(* Logix 5000 project; controller EFlo_iQ_Controller vendor 1 type 14 code 74 rev 20.12; software revision 20.01 *)

TASK MainTask (continuous, watchdog 500 ms) : MainProgram

MODULES
   Local : vendor 1 type 14 code 74 (1768Ctrl5Slot 0, Compact 0, rev 20.12)
      ENET : 1768-ENBT (1768 1, Ethernet 10.10.20.11, rev 3.1)
         EFlo_iQ : ETHERNET-MODULE (Ethernet 10.10.20.16, rev 1.1, Output RPI 10 ms)   // Graco E-Flo iQ Pico Map
END_MODULES

TYPE EFlo_iQ_Control_Bits :
STRUCT
   SystemEnableRequest : BOOL;
   SystemDisableRequest : BOOL;
   PLCLockoutRequest : BOOL;
   StyleEnableSignal : BOOL;
   StyleGoSignal : BOOL;
   StyleDispenseCompleted : BOOL;
   TandemCrossoverRequest : BOOL;
END_STRUCT
END_TYPE

TYPE EFlo_iQ_HeartbeatLogic :
STRUCT
   HeartbeatFailure : BOOL;
   EFlo_iQ_Disconnected : BOOL;
   Heartbeat_HighMonitor : COUNTER;
   Heartbeat_LowMonitor : COUNTER;
   Heartbeat_MonitorTimer : TIMER;
   Heartbeat_StopMonitorTimer : BOOL;
END_STRUCT
END_TYPE

TYPE EFlo_iQ_Status_Bits :
STRUCT
   Heartbeat : BOOL;
   AutomationReady : BOOL;
   PLCControlActive : BOOL;
   SystemActive : BOOL;
   NoAlarmsPresent : BOOL;
   NoDeviationsPresent : BOOL;
   NoAdvisoriesPresent : BOOL;
   SystemReady : BOOL;
   PrechargeDechargeActive : BOOL;
   DispenseInProcess : BOOL;
   DrumIsLow : BOOL;
   DrumIsEmpty : BOOL;
   PumpNotPrimed : BOOL;
END_STRUCT
END_TYPE

TYPE EFlo_iQ_StyleRequest :
STRUCT
   DesiredStyleNumber : DINT;
   DesiredStylePrecharge : DINT;   // XXXX.X bars
   DesiredStyleFlowrate : DINT;   // XXXX cc/min
   DesiredStyleShot : DINT;   // XXXX.XX cc
END_STRUCT
END_TYPE

VAR_GLOBAL   (* controller tags *)
   EFlo_iQ_Control_Bits : EFlo_iQ_Control_Bits; {access Read Only}
   EFlo_iQ_HeartbeatLogic : EFlo_iQ_HeartbeatLogic := (Heartbeat_HighMonitor.PRE := 2, Heartbeat_LowMonitor.PRE := 2, Heartbeat_MonitorTimer.PRE := 20000); {access Read Only}
   EFlo_iQ_Status_Bits : EFlo_iQ_Status_Bits; {access Read Only}
   EFlo_iQ_StyleRequest : EFlo_iQ_StyleRequest; {access Read Only}
END_VAR

PROGRAM MainProgram   (* main routine MainRoutine *)

ROUTINE MainRoutine   (* ladder *)
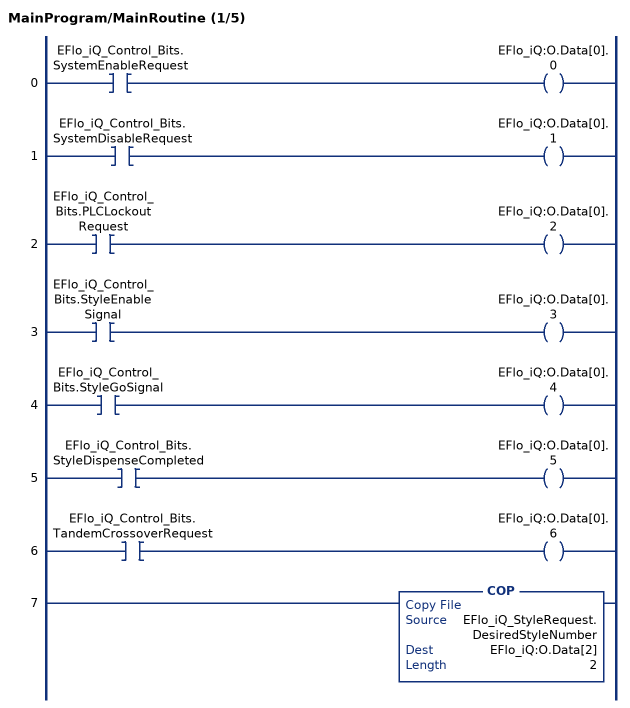
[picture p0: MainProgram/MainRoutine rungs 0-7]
   0: XIC(EFlo_iQ_Control_Bits.SystemEnableRequest)OTE(EFlo_iQ:O.Data[0].0);
   1: XIC(EFlo_iQ_Control_Bits.SystemDisableRequest)OTE(EFlo_iQ:O.Data[0].1);
   2: XIC(EFlo_iQ_Control_Bits.PLCLockoutRequest)OTE(EFlo_iQ:O.Data[0].2);
   3: XIC(EFlo_iQ_Control_Bits.StyleEnableSignal)OTE(EFlo_iQ:O.Data[0].3);
   4: XIC(EFlo_iQ_Control_Bits.StyleGoSignal)OTE(EFlo_iQ:O.Data[0].4);
   5: XIC(EFlo_iQ_Control_Bits.StyleDispenseCompleted)OTE(EFlo_iQ:O.Data[0].5);
   6: XIC(EFlo_iQ_Control_Bits.TandemCrossoverRequest)OTE(EFlo_iQ:O.Data[0].6);
   7: COP(EFlo_iQ_StyleRequest.DesiredStyleNumber,EFlo_iQ:O.Data[2],2);
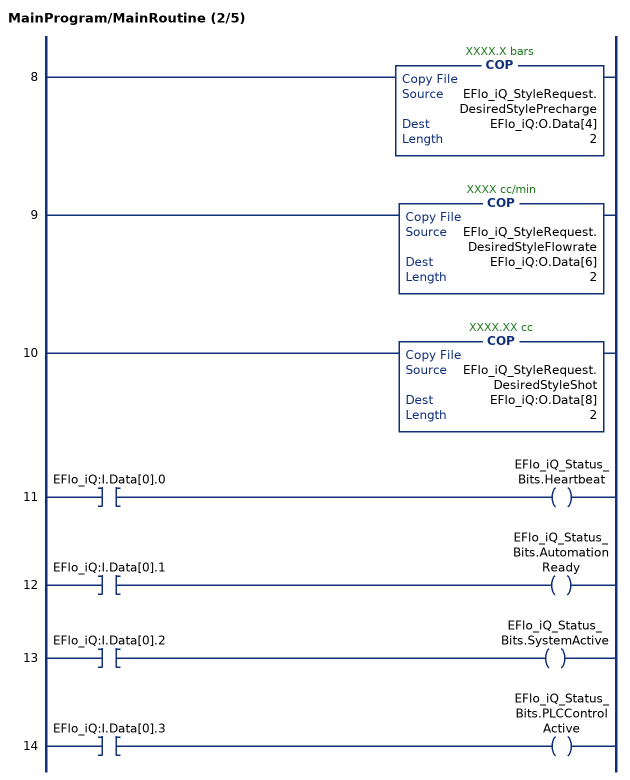
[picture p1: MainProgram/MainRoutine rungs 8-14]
   8: COP(EFlo_iQ_StyleRequest.DesiredStylePrecharge,EFlo_iQ:O.Data[4],2);
   9: COP(EFlo_iQ_StyleRequest.DesiredStyleFlowrate,EFlo_iQ:O.Data[6],2);
   10: COP(EFlo_iQ_StyleRequest.DesiredStyleShot,EFlo_iQ:O.Data[8],2);
   11: XIC(EFlo_iQ:I.Data[0].0)OTE(EFlo_iQ_Status_Bits.Heartbeat);
   12: XIC(EFlo_iQ:I.Data[0].1)OTE(EFlo_iQ_Status_Bits.AutomationReady);
   13: XIC(EFlo_iQ:I.Data[0].2)OTE(EFlo_iQ_Status_Bits.SystemActive);
   14: XIC(EFlo_iQ:I.Data[0].3)OTE(EFlo_iQ_Status_Bits.PLCControlActive);
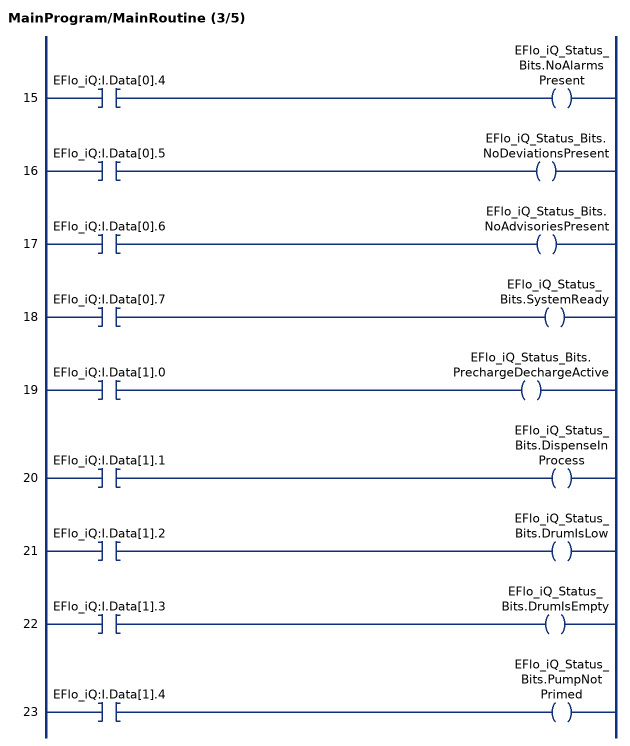
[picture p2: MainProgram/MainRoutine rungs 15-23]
   15: XIC(EFlo_iQ:I.Data[0].4)OTE(EFlo_iQ_Status_Bits.NoAlarmsPresent);
   16: XIC(EFlo_iQ:I.Data[0].5)OTE(EFlo_iQ_Status_Bits.NoDeviationsPresent);
   17: XIC(EFlo_iQ:I.Data[0].6)OTE(EFlo_iQ_Status_Bits.NoAdvisoriesPresent);
   18: XIC(EFlo_iQ:I.Data[0].7)OTE(EFlo_iQ_Status_Bits.SystemReady);
   19: XIC(EFlo_iQ:I.Data[1].0)OTE(EFlo_iQ_Status_Bits.PrechargeDechargeActive);
   20: XIC(EFlo_iQ:I.Data[1].1)OTE(EFlo_iQ_Status_Bits.DispenseInProcess);
   21: XIC(EFlo_iQ:I.Data[1].2)OTE(EFlo_iQ_Status_Bits.DrumIsLow);
   22: XIC(EFlo_iQ:I.Data[1].3)OTE(EFlo_iQ_Status_Bits.DrumIsEmpty);
   23: XIC(EFlo_iQ:I.Data[1].4)OTE(EFlo_iQ_Status_Bits.PumpNotPrimed);
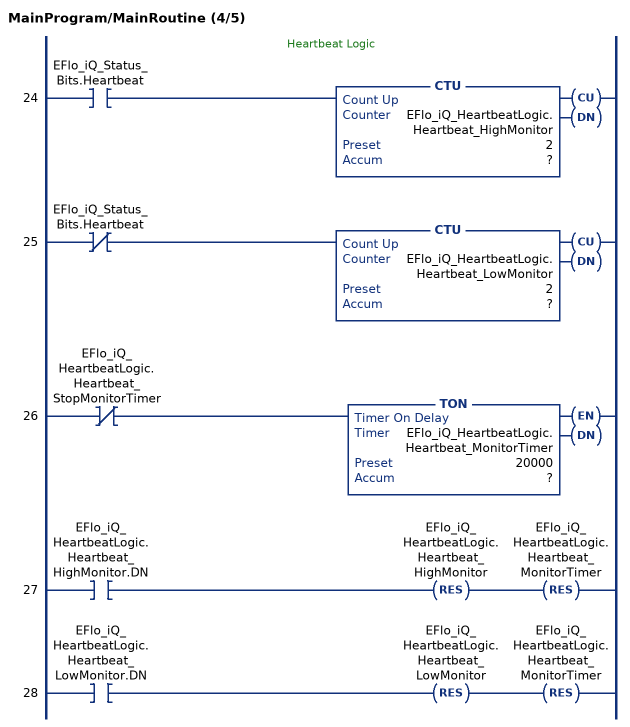
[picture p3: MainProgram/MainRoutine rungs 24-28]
   // Heartbeat Logic
   24: XIC(EFlo_iQ_Status_Bits.Heartbeat)CTU(EFlo_iQ_HeartbeatLogic.Heartbeat_HighMonitor,?,?);
   25: XIO(EFlo_iQ_Status_Bits.Heartbeat)CTU(EFlo_iQ_HeartbeatLogic.Heartbeat_LowMonitor,?,?);
   26: XIO(EFlo_iQ_HeartbeatLogic.Heartbeat_StopMonitorTimer)TON(EFlo_iQ_HeartbeatLogic.Heartbeat_MonitorTimer,?,?);
   27: XIC(EFlo_iQ_HeartbeatLogic.Heartbeat_HighMonitor.DN)RES(EFlo_iQ_HeartbeatLogic.Heartbeat_HighMonitor)RES(EFlo_iQ_HeartbeatLogic.Heartbeat_MonitorTimer);
   28: XIC(EFlo_iQ_HeartbeatLogic.Heartbeat_LowMonitor.DN)RES(EFlo_iQ_HeartbeatLogic.Heartbeat_LowMonitor)RES(EFlo_iQ_HeartbeatLogic.Heartbeat_MonitorTimer);
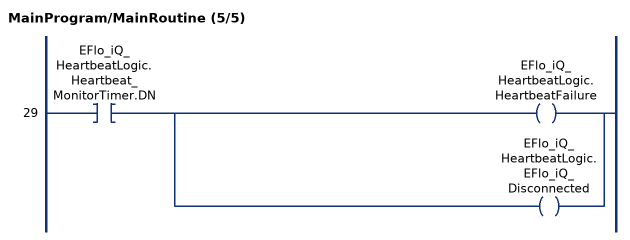
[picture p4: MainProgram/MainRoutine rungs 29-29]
   29: XIC(EFlo_iQ_HeartbeatLogic.Heartbeat_MonitorTimer.DN)[OTE(EFlo_iQ_HeartbeatLogic.HeartbeatFailure) ,OTE(EFlo_iQ_HeartbeatLogic.EFlo_iQ_Disconnected) ];
END_ROUTINE
END_PROGRAM
